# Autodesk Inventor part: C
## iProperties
Created: 2007-08
Part Number: C
Document SubType Name: Modeling
Designer: t-ikumi
Density: 1 g/cm^3
Author: t-ikumi
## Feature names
1. 押し出し1 [Extrusion]
2. 押し出し2 [Extrusion]
3. 押し出し3 [Extrusion]
4. 面取り1 [Chamfer]
5. 押し出し4 [Extrusion]
6. フィレット1 [Fillet]
